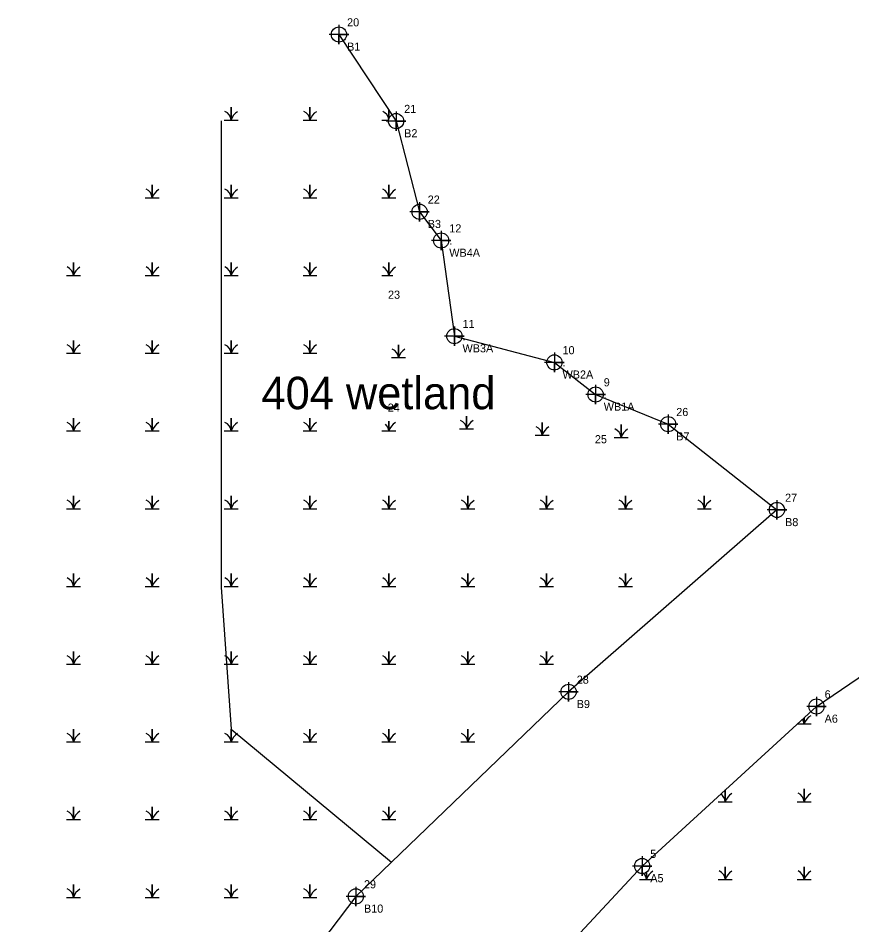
# Model space of a CAD drawing. Extents: x 2678633 to 2679425, y 623836 to 624637.
# Drawn here: x 2678971 to 2679228, y 624356.4 to 624635.8 of the extents above; entities that cross this region are included whole.
import ezdxf

# ---------------------------------------------------------------- set-up
doc = ezdxf.new("R2010")
doc.units = 0
for name, color, linetype in [('Exist Environmental Wetland Boundary', 7, 'Continuous'), ('Exist Environmental Wetland Boundary Cogo Comment', 7, 'Continuous'), ('Exist Environmental Wetland Boundary Cogo Elevation', 7, 'Continuous'), ('Exist Environmental Wetland Boundary Cogo Number', 7, 'Continuous'), ('Exist Environmental Wetland Boundary Cogo Point CELL', 7, 'Continuous'), ('Exist Environmental Wetland Boundary Text', 7, 'Continuous'), ('Exist Hydro Swamp or Marsh', 7, 'Continuous')]:
    doc.layers.add(name, color=color, linetype=linetype)

msp = doc.modelspace()

# ---------------------------------------------------------------- linework, layer by layer
at = {"layer": 'Exist Environmental Wetland Boundary'}
for points in [[(2679069.93, 624630.75), (2679087.52, 624604.07), (2679094.78, 624576.13), (2679101.43, 624567.27), (2679105.5, 624537.81), (2679136.33, 624529.73), (2679149.04, 624519.84), (2679171.39, 624510.69), (2679204.94, 624484.27), (2679140.71, 624428.23), (2679075.13, 624365.19), (2679029.64, 624305.05), (2678988.85, 624240.45), (2678945.79, 624182.95), (2678958.22, 624173.09)], [(2679033.61, 624604.18), (2679033.61, 624460.48), (2679036.68, 624416.75), (2679086.11, 624375.75)], [(2678996.94, 624177.71), (2679033.89, 624182.51), (2679071.36, 624253.6), (2679114.38, 624321.81), (2679163.39, 624374.56), (2679217.13, 624423.71), (2679286.14, 624470.62), (2679307.52, 624474.8), (2679321.51, 624489.84), (2679302.84, 624456.53), (2679292.78, 624438.21), (2679296.8, 624418.87), (2679319.66, 624396.04), (2679331.43, 624377.88), (2679317.29, 624347.71), (2679323.72, 624307.13), (2679356.11, 624275.91), (2679393.07, 624264.72), (2679417.04, 624216.21)]]:
    msp.add_lwpolyline(points, dxfattribs=at)
at = {"layer": 'Exist Environmental Wetland Boundary Cogo Point CELL'}
for points in [[(2679069.93, 624633.75), (2679069.93, 624627.75), (2679069.93, 624630.75), (2679072.93, 624630.75), (2679066.93, 624630.75)], [(2679087.52, 624607.07), (2679087.52, 624601.07), (2679087.52, 624604.07), (2679090.52, 624604.07), (2679084.52, 624604.07)], [(2679094.78, 624579.13), (2679094.78, 624573.13), (2679094.78, 624576.13), (2679097.78, 624576.13), (2679091.78, 624576.13)], [(2679101.43, 624570.27), (2679101.43, 624564.27), (2679101.43, 624567.27), (2679104.43, 624567.27), (2679098.43, 624567.27)], [(2679105.5, 624540.81), (2679105.5, 624534.81), (2679105.5, 624537.81), (2679108.5, 624537.81), (2679102.5, 624537.81)], [(2679136.33, 624532.73), (2679136.33, 624526.73), (2679136.33, 624529.73), (2679139.33, 624529.73), (2679133.33, 624529.73)], [(2679149.04, 624522.84), (2679149.04, 624516.84), (2679149.04, 624519.84), (2679152.04, 624519.84), (2679146.04, 624519.84)], [(2679171.39, 624513.69), (2679171.39, 624507.69), (2679171.39, 624510.69), (2679174.39, 624510.69), (2679168.39, 624510.69)], [(2679204.94, 624487.27), (2679204.94, 624481.27), (2679204.94, 624484.27), (2679207.94, 624484.27), (2679201.94, 624484.27)], [(2679140.71, 624431.23), (2679140.71, 624425.23), (2679140.71, 624428.23), (2679143.71, 624428.23), (2679137.71, 624428.23)], [(2679217.13, 624426.71), (2679217.13, 624420.71), (2679217.13, 624423.71), (2679220.13, 624423.71), (2679214.13, 624423.71)], [(2679163.39, 624377.56), (2679163.39, 624371.56), (2679163.39, 624374.56), (2679166.39, 624374.56), (2679160.39, 624374.56)], [(2679075.13, 624368.19), (2679075.13, 624362.19), (2679075.13, 624365.19), (2679078.13, 624365.19), (2679072.13, 624365.19)]]:
    msp.add_lwpolyline(points, dxfattribs=at)
for centre in [(2679069.93, 624630.75), (2679087.52, 624604.07), (2679094.78, 624576.13), (2679101.43, 624567.27), (2679105.5, 624537.81), (2679136.33, 624529.73), (2679149.04, 624519.84), (2679171.39, 624510.69), (2679204.94, 624484.27), (2679140.71, 624428.23), (2679217.13, 624423.71), (2679163.39, 624374.56), (2679075.13, 624365.19)]:
    msp.add_circle(centre, 2.34, dxfattribs=at)
at = {"layer": 'Exist Hydro Swamp or Marsh'}
for p, q in [((2679088.26, 624533.01), (2679088.26, 624533.01)), ((2679109.27, 624511.01), (2679109.27, 624511.01)), ((2679132.58, 624509.04), (2679132.58, 624509.04)), ((2679156.88, 624508.39), (2679156.88, 624508.39))]:
    msp.add_line(p, q, dxfattribs=at)
for points in [[(2679034.53, 624604.4), (2679036.68, 624604.4), (2679036.68, 624608.35), (2679036.68, 624604.4), (2679038.83, 624604.4)], [(2679058.84, 624604.4), (2679060.99, 624604.4), (2679060.99, 624608.35), (2679060.99, 624604.4), (2679063.14, 624604.4)], [(2679085.3, 624604.7), (2679085.3, 624607.44)], [(2679085.3, 624607.44), (2679085.3, 624604.7)], [(2679083.15, 624604.4), (2679085.25, 624604.4)], [(2679010.22, 624580.45), (2679012.37, 624580.45), (2679012.37, 624584.4), (2679012.37, 624580.45), (2679014.52, 624580.45)], [(2679034.53, 624580.45), (2679036.68, 624580.45), (2679036.68, 624584.4), (2679036.68, 624580.45), (2679038.83, 624580.45)], [(2679058.84, 624580.45), (2679060.99, 624580.45), (2679060.99, 624584.4), (2679060.99, 624580.45), (2679063.14, 624580.45)], [(2679083.15, 624580.45), (2679085.3, 624580.45), (2679085.3, 624584.4), (2679085.3, 624580.45), (2679087.45, 624580.45)], [(2678985.9, 624556.5), (2678988.05, 624556.5), (2678988.05, 624560.45), (2678988.05, 624556.5), (2678990.2, 624556.5)], [(2679010.22, 624556.5), (2679012.37, 624556.5), (2679012.37, 624560.45), (2679012.37, 624556.5), (2679014.52, 624556.5)], [(2679034.53, 624556.5), (2679036.68, 624556.5), (2679036.68, 624560.45), (2679036.68, 624556.5), (2679038.83, 624556.5)], [(2679058.84, 624556.5), (2679060.99, 624556.5), (2679060.99, 624560.45), (2679060.99, 624556.5), (2679063.14, 624556.5)], [(2679083.15, 624556.5), (2679085.3, 624556.5), (2679085.3, 624560.45), (2679085.3, 624556.5), (2679086.58, 624556.5)], [(2678985.9, 624532.55), (2678988.05, 624532.55), (2678988.05, 624536.5), (2678988.05, 624532.55), (2678990.2, 624532.55)], [(2679010.22, 624532.55), (2679012.37, 624532.55), (2679012.37, 624536.5), (2679012.37, 624532.55), (2679014.52, 624532.55)], [(2679034.53, 624532.55), (2679036.68, 624532.55), (2679036.68, 624536.5), (2679036.68, 624532.55), (2679038.83, 624532.55)], [(2679058.84, 624532.55), (2679060.99, 624532.55), (2679060.99, 624536.5), (2679060.99, 624532.55), (2679063.14, 624532.55)], [(2679086.11, 624531.23), (2679088.26, 624531.23), (2679088.26, 624535.17), (2679088.26, 624531.23), (2679090.41, 624531.23)], [(2678985.9, 624508.6), (2678988.05, 624508.6), (2678988.05, 624512.55), (2678988.05, 624508.6), (2678990.2, 624508.6)], [(2679010.22, 624508.6), (2679012.37, 624508.6), (2679012.37, 624512.55), (2679012.37, 624508.6), (2679014.52, 624508.6)], [(2679034.53, 624508.6), (2679036.68, 624508.6), (2679036.68, 624512.55), (2679036.68, 624508.6), (2679038.83, 624508.6)], [(2679058.84, 624508.6), (2679060.99, 624508.6), (2679060.99, 624512.55), (2679060.99, 624508.6), (2679063.14, 624508.6)], [(2679083.15, 624508.6), (2679085.3, 624508.6), (2679085.3, 624511.61)], [(2679085.3, 624511.61), (2679085.3, 624508.6), (2679087.45, 624508.6)], [(2679107.12, 624509.23), (2679109.27, 624509.23), (2679109.27, 624513.18), (2679109.27, 624509.23), (2679111.42, 624509.23)], [(2679130.43, 624507.26), (2679132.58, 624507.26), (2679132.58, 624511.21), (2679132.58, 624507.26), (2679134.73, 624507.26)], [(2679154.73, 624506.6), (2679156.88, 624506.6), (2679156.88, 624510.55), (2679156.88, 624506.6), (2679159.03, 624506.6)], [(2678985.9, 624484.65), (2678988.05, 624484.65), (2678988.05, 624488.6), (2678988.05, 624484.65), (2678990.2, 624484.65)], [(2679010.22, 624484.65), (2679012.37, 624484.65), (2679012.37, 624488.6), (2679012.37, 624484.65), (2679014.52, 624484.65)], [(2679034.53, 624484.65), (2679036.68, 624484.65), (2679036.68, 624488.6), (2679036.68, 624484.65), (2679038.83, 624484.65)], [(2679058.84, 624484.65), (2679060.99, 624484.65), (2679060.99, 624488.6), (2679060.99, 624484.65), (2679063.14, 624484.65)], [(2679083.15, 624484.65), (2679085.3, 624484.65), (2679085.3, 624488.6), (2679085.3, 624484.65), (2679087.45, 624484.65)], [(2679107.47, 624484.65), (2679109.62, 624484.65), (2679109.62, 624488.6), (2679109.62, 624484.65), (2679111.77, 624484.65)], [(2679131.78, 624484.65), (2679133.93, 624484.65), (2679133.93, 624488.6), (2679133.93, 624484.65), (2679136.08, 624484.65)], [(2679156.09, 624484.65), (2679158.24, 624484.65), (2679158.24, 624488.6), (2679158.24, 624484.65), (2679160.39, 624484.65)], [(2679180.4, 624484.65), (2679182.55, 624484.65), (2679182.55, 624488.6), (2679182.55, 624484.65), (2679184.7, 624484.65)], [(2678985.9, 624460.7), (2678988.05, 624460.7), (2678988.05, 624464.65), (2678988.05, 624460.7), (2678990.2, 624460.7)], [(2679010.22, 624460.7), (2679012.37, 624460.7), (2679012.37, 624464.65), (2679012.37, 624460.7), (2679014.52, 624460.7)], [(2679034.53, 624460.7), (2679036.68, 624460.7), (2679036.68, 624464.65), (2679036.68, 624460.7), (2679038.83, 624460.7)], [(2679058.84, 624460.7), (2679060.99, 624460.7), (2679060.99, 624464.65), (2679060.99, 624460.7), (2679063.14, 624460.7)], [(2679083.15, 624460.7), (2679085.3, 624460.7), (2679085.3, 624464.65), (2679085.3, 624460.7), (2679087.45, 624460.7)], [(2679107.47, 624460.7), (2679109.62, 624460.7), (2679109.62, 624464.65), (2679109.62, 624460.7), (2679111.77, 624460.7)], [(2679131.78, 624460.7), (2679133.93, 624460.7), (2679133.93, 624464.65), (2679133.93, 624460.7), (2679136.08, 624460.7)], [(2679156.09, 624460.7), (2679158.24, 624460.7), (2679158.24, 624464.65), (2679158.24, 624460.7), (2679160.39, 624460.7)], [(2678985.9, 624436.75), (2678988.05, 624436.75), (2678988.05, 624440.7), (2678988.05, 624436.75), (2678990.2, 624436.75)], [(2679010.22, 624436.75), (2679012.37, 624436.75), (2679012.37, 624440.7), (2679012.37, 624436.75), (2679014.52, 624436.75)], [(2679034.53, 624436.75), (2679036.68, 624436.75), (2679036.68, 624440.7), (2679036.68, 624436.75), (2679038.83, 624436.75)], [(2679058.84, 624436.75), (2679060.99, 624436.75), (2679060.99, 624440.7), (2679060.99, 624436.75), (2679063.14, 624436.75)], [(2679083.15, 624436.75), (2679085.3, 624436.75), (2679085.3, 624440.7), (2679085.3, 624436.75), (2679087.45, 624436.75)], [(2679107.47, 624436.75), (2679109.62, 624436.75), (2679109.62, 624440.7), (2679109.62, 624436.75), (2679111.77, 624436.75)], [(2679131.78, 624436.75), (2679133.93, 624436.75), (2679133.93, 624440.7), (2679133.93, 624436.75), (2679136.08, 624436.75)], [(2679211.23, 624418.32), (2679213.33, 624418.32), (2679213.33, 624420.24)], [(2679213.33, 624420.24), (2679213.33, 624418.32), (2679215.48, 624418.32)], [(2678985.9, 624412.8), (2678988.05, 624412.8), (2678988.05, 624416.75), (2678988.05, 624412.8), (2678990.2, 624412.8)], [(2679010.22, 624412.8), (2679012.37, 624412.8), (2679012.37, 624416.75), (2679012.37, 624412.8), (2679014.52, 624412.8)], [(2679034.53, 624412.8), (2679036.68, 624412.8), (2679036.68, 624416.75), (2679036.68, 624412.8), (2679038.83, 624412.8)], [(2679058.84, 624412.8), (2679060.99, 624412.8), (2679060.99, 624416.75), (2679060.99, 624412.8), (2679063.14, 624412.8)], [(2679083.15, 624412.8), (2679085.3, 624412.8), (2679085.3, 624416.75), (2679085.3, 624412.8), (2679087.45, 624412.8)], [(2679107.47, 624412.8), (2679109.62, 624412.8), (2679109.62, 624416.75), (2679109.62, 624412.8), (2679111.77, 624412.8)], [(2679186.86, 624394.37), (2679189.01, 624394.37), (2679189.01, 624398)], [(2679189.01, 624398), (2679189.01, 624394.37), (2679191.17, 624394.37)], [(2679211.18, 624394.37), (2679213.33, 624394.37), (2679213.33, 624398.31), (2679213.33, 624394.37), (2679215.48, 624394.37)], [(2678985.9, 624388.85), (2678988.05, 624388.85), (2678988.05, 624392.8), (2678988.05, 624388.85), (2678990.2, 624388.85)], [(2679010.22, 624388.85), (2679012.37, 624388.85), (2679012.37, 624392.8), (2679012.37, 624388.85), (2679014.52, 624388.85)], [(2679034.53, 624388.85), (2679036.68, 624388.85), (2679036.68, 624392.8), (2679036.68, 624388.85), (2679038.83, 624388.85)], [(2679058.84, 624388.85), (2679060.99, 624388.85), (2679060.99, 624392.8), (2679060.99, 624388.85), (2679063.14, 624388.85)], [(2679083.15, 624388.85), (2679085.3, 624388.85), (2679085.3, 624392.8), (2679085.3, 624388.85), (2679087.45, 624388.85)], [(2679186.86, 624370.42), (2679189.01, 624370.42), (2679189.01, 624374.36), (2679189.01, 624370.42), (2679191.17, 624370.42)], [(2679211.18, 624370.42), (2679213.33, 624370.42), (2679213.33, 624374.36), (2679213.33, 624370.42), (2679215.48, 624370.42)], [(2679162.55, 624370.42), (2679164.7, 624370.42), (2679164.7, 624372.67)], [(2679164.7, 624372.67), (2679164.7, 624370.42), (2679166.85, 624370.42)], [(2678985.9, 624364.9), (2678988.05, 624364.9), (2678988.05, 624368.85), (2678988.05, 624364.9), (2678990.2, 624364.9)], [(2679010.22, 624364.9), (2679012.37, 624364.9), (2679012.37, 624368.85), (2679012.37, 624364.9), (2679014.52, 624364.9)], [(2679034.53, 624364.9), (2679036.68, 624364.9), (2679036.68, 624368.85), (2679036.68, 624364.9), (2679038.83, 624364.9)], [(2679058.84, 624364.9), (2679060.99, 624364.9), (2679060.99, 624368.85), (2679060.99, 624364.9), (2679063.14, 624364.9)]]:
    msp.add_lwpolyline(points, dxfattribs=at)
for centre, radius, start, end in [((2679033.61, 624604.18), 3.07, 4.1403, 67.535), ((2679041.24, 624602.89), 4.81, 122.1274, 161.6222), ((2679057.92, 624604.18), 3.07, 4.1403, 67.535), ((2679065.55, 624602.89), 4.81, 122.1274, 161.6222), ((2679082.24, 624604.18), 3.07, 7.7072, 67.535), ((2679089.86, 624602.89), 4.81, 139.1466, 139.8748), ((2679009.3, 624580.23), 3.07, 4.1403, 67.535), ((2679033.61, 624580.23), 3.07, 4.1403, 67.535), ((2679057.92, 624580.23), 3.07, 4.1403, 67.535), ((2679082.24, 624580.23), 3.07, 4.1403, 67.535), ((2679016.93, 624578.94), 4.81, 122.1274, 161.6222), ((2679041.24, 624578.94), 4.81, 122.1274, 161.6222), ((2679065.55, 624578.94), 4.81, 122.1274, 161.6222), ((2679089.86, 624578.94), 4.81, 122.1274, 161.6222), ((2678984.99, 624556.28), 3.07, 4.1403, 67.535), ((2678992.61, 624554.99), 4.81, 122.1274, 161.6222), ((2679009.3, 624556.28), 3.07, 4.1403, 67.535), ((2679016.93, 624554.99), 4.81, 122.1274, 161.6222), ((2679033.61, 624556.28), 3.07, 4.1403, 67.535), ((2679041.24, 624554.99), 4.81, 122.1274, 161.6222), ((2679057.92, 624556.28), 3.07, 4.1403, 67.535), ((2679065.55, 624554.99), 4.81, 122.1274, 161.6222), ((2679082.24, 624556.28), 3.07, 4.1403, 67.535), ((2679089.86, 624554.99), 4.81, 122.1274, 161.6222), ((2678984.99, 624532.33), 3.07, 4.1403, 67.535), ((2678992.61, 624531.04), 4.81, 122.1274, 161.6222), ((2679009.3, 624532.33), 3.07, 4.1403, 67.535), ((2679016.93, 624531.04), 4.81, 122.1274, 161.6222), ((2679033.61, 624532.33), 3.07, 4.1403, 67.535), ((2679041.24, 624531.04), 4.81, 122.1274, 161.6222), ((2679057.92, 624532.33), 3.07, 4.1403, 67.535), ((2679065.55, 624531.04), 4.81, 122.1274, 161.6222), ((2679085.19, 624531.01), 3.07, 4.1403, 67.535), ((2679092.82, 624529.71), 4.81, 122.1274, 161.6222), ((2678984.99, 624508.38), 3.07, 4.1403, 67.535), ((2678992.61, 624507.09), 4.81, 122.1274, 161.6222), ((2679009.3, 624508.38), 3.07, 4.1403, 67.535), ((2679016.93, 624507.09), 4.81, 122.1274, 161.6222), ((2679033.61, 624508.38), 3.07, 4.1403, 67.535), ((2679041.24, 624507.09), 4.81, 122.1274, 161.6222), ((2679057.92, 624508.38), 3.07, 4.1403, 67.535), ((2679065.55, 624507.09), 4.81, 122.1274, 161.6222), ((2679082.24, 624508.38), 3.07, 4.1403, 47.7553), ((2679089.86, 624507.09), 4.81, 122.1274, 161.6222), ((2679106.21, 624509.01), 3.07, 4.1403, 67.535), ((2679113.83, 624507.72), 4.81, 122.1274, 161.6222), ((2679129.52, 624507.04), 3.07, 4.1403, 67.535), ((2679137.14, 624505.75), 4.81, 122.1274, 161.6222), ((2679153.81, 624506.38), 3.07, 4.1403, 67.535), ((2679161.44, 624505.09), 4.81, 122.1274, 161.6222), ((2678984.99, 624484.43), 3.07, 4.1403, 67.535), ((2678992.61, 624483.14), 4.81, 122.1274, 161.6222), ((2679009.3, 624484.43), 3.07, 4.1403, 67.535), ((2679016.93, 624483.14), 4.81, 122.1274, 161.6222), ((2679033.61, 624484.43), 3.07, 4.1403, 67.535), ((2679041.24, 624483.14), 4.81, 122.1274, 161.6222), ((2679057.92, 624484.43), 3.07, 4.1403, 67.535), ((2679065.55, 624483.14), 4.81, 122.1274, 161.6222), ((2679082.24, 624484.43), 3.07, 4.1403, 67.535), ((2679089.86, 624483.14), 4.81, 122.1274, 161.6222), ((2679106.55, 624484.43), 3.07, 4.1403, 67.535), ((2679114.18, 624483.14), 4.81, 122.1274, 161.6222), ((2679130.86, 624484.43), 3.07, 4.1403, 67.535), ((2679138.49, 624483.14), 4.81, 122.1274, 161.6222), ((2679155.17, 624484.43), 3.07, 4.1403, 67.535), ((2679162.8, 624483.14), 4.81, 122.1274, 161.6222), ((2679179.49, 624484.43), 3.07, 4.1403, 67.535), ((2679187.11, 624483.14), 4.81, 122.1274, 161.6222), ((2678984.99, 624460.48), 3.07, 4.1403, 67.535), ((2678992.61, 624459.19), 4.81, 122.1274, 161.6222), ((2679009.3, 624460.48), 3.07, 4.1403, 67.535), ((2679016.93, 624459.19), 4.81, 122.1274, 161.6222), ((2679033.61, 624460.48), 3.07, 4.1403, 67.535), ((2679041.24, 624459.19), 4.81, 122.1274, 161.6222), ((2679057.92, 624460.48), 3.07, 4.1403, 67.535), ((2679065.55, 624459.19), 4.81, 122.1274, 161.6222), ((2679082.24, 624460.48), 3.07, 4.1403, 67.535), ((2679089.86, 624459.19), 4.81, 122.1274, 161.6222), ((2679106.55, 624460.48), 3.07, 4.1403, 67.535), ((2679114.18, 624459.19), 4.81, 122.1274, 161.6222), ((2679130.86, 624460.48), 3.07, 4.1403, 67.535), ((2679138.49, 624459.19), 4.81, 122.1274, 161.6222), ((2679155.17, 624460.48), 3.07, 4.1403, 67.535), ((2679162.8, 624459.19), 4.81, 122.1274, 161.6222), ((2679179.49, 624460.48), 3.07, 63.9969, 67.535), ((2678984.99, 624436.53), 3.07, 4.1403, 67.535), ((2678992.61, 624435.24), 4.81, 122.1274, 161.6222), ((2679009.3, 624436.53), 3.07, 4.1403, 67.535), ((2679016.93, 624435.24), 4.81, 122.1274, 161.6222), ((2679033.61, 624436.53), 3.07, 4.1403, 67.535), ((2679041.24, 624435.24), 4.81, 122.1274, 161.6222), ((2679057.92, 624436.53), 3.07, 4.1403, 67.535), ((2679065.55, 624435.24), 4.81, 122.1274, 161.6222), ((2679082.24, 624436.53), 3.07, 4.1403, 67.535), ((2679089.86, 624435.24), 4.81, 122.1274, 161.6222), ((2679106.55, 624436.53), 3.07, 4.1403, 67.535), ((2679114.18, 624435.24), 4.81, 122.1274, 161.6222), ((2679130.86, 624436.53), 3.07, 4.1403, 67.535), ((2679138.49, 624435.24), 4.81, 122.1274, 161.6222), ((2679210.26, 624418.1), 3.07, 4.1403, 33.2476), ((2679217.89, 624416.8), 4.81, 122.1274, 161.6222), ((2678984.99, 624412.58), 3.07, 4.1403, 67.535), ((2679009.3, 624412.58), 3.07, 4.1403, 67.535), ((2679033.61, 624412.58), 3.07, 4.1403, 67.535), ((2679057.92, 624412.58), 3.07, 4.1403, 67.535), ((2679082.24, 624412.58), 3.07, 4.1403, 67.535), ((2679106.55, 624412.58), 3.07, 4.1403, 67.535), ((2678992.61, 624411.29), 4.81, 122.1274, 161.6222), ((2679016.93, 624411.29), 4.81, 122.1274, 161.6222), ((2679041.24, 624411.29), 4.81, 122.1274, 161.6222), ((2679065.55, 624411.29), 4.81, 122.1274, 161.6222), ((2679089.86, 624411.29), 4.81, 122.1274, 161.6222), ((2679114.18, 624411.29), 4.81, 122.1274, 161.6222), ((2679185.95, 624394.15), 3.07, 4.1403, 56.9801), ((2679193.58, 624392.85), 4.81, 122.1274, 161.6222), ((2679210.26, 624394.15), 3.07, 4.1403, 67.535), ((2679217.89, 624392.85), 4.81, 122.1274, 161.6222), ((2678984.99, 624388.63), 3.07, 4.1403, 67.535), ((2678992.61, 624387.34), 4.81, 122.1274, 161.6222), ((2679009.3, 624388.63), 3.07, 4.1403, 67.535), ((2679016.93, 624387.34), 4.81, 122.1274, 161.6222), ((2679033.61, 624388.63), 3.07, 4.1403, 67.535), ((2679041.24, 624387.34), 4.81, 122.1274, 161.6222), ((2679057.92, 624388.63), 3.07, 4.1403, 67.535), ((2679065.55, 624387.34), 4.81, 122.1274, 161.6222), ((2679082.24, 624388.63), 3.07, 4.1403, 67.535), ((2679089.86, 624387.34), 4.81, 122.1274, 161.6222), ((2679161.64, 624370.2), 3.07, 4.1403, 43.3721), ((2679169.26, 624368.9), 4.81, 122.1274, 161.6222), ((2679185.95, 624370.2), 3.07, 4.1403, 67.535), ((2679193.58, 624368.9), 4.81, 122.1274, 161.6222), ((2679210.26, 624370.2), 3.07, 4.1403, 67.535), ((2679217.89, 624368.9), 4.81, 122.1274, 161.6222), ((2678984.99, 624364.68), 3.07, 4.1403, 67.535), ((2678992.61, 624363.39), 4.81, 122.1274, 161.6222), ((2679009.3, 624364.68), 3.07, 4.1403, 67.535), ((2679016.93, 624363.39), 4.81, 122.1274, 161.6222), ((2679033.61, 624364.68), 3.07, 4.1403, 67.535), ((2679041.24, 624363.39), 4.81, 122.1274, 161.6222), ((2679057.92, 624364.68), 3.07, 4.1403, 67.535), ((2679065.55, 624363.39), 4.81, 122.1274, 161.6222)]:
    msp.add_arc(centre, radius, start, end, dxfattribs=at)

# ---------------------------------------------------------------- texts
at = {"layer": 'Exist Environmental Wetland Boundary Cogo Comment'}
for s, p in [('B1', (2679072.43, 624625.75)), ('B2', (2679090.02, 624599.07)), ('B3', (2679097.28, 624571.13)), ('WB4A', (2679103.93, 624562.27)), ('WB3A', (2679108, 624532.81)), ('WB2A', (2679138.83, 624524.73)), ('WB1A', (2679151.54, 624514.84)), ('B7', (2679173.89, 624505.69)), ('B8', (2679207.44, 624479.27)), ('B9', (2679143.21, 624423.23)), ('A6', (2679219.63, 624418.71)), ('A5', (2679165.89, 624369.56)), ('B10', (2679077.63, 624360.19))]:
    msp.add_text(s, height=2.5, dxfattribs=at).set_placement(p)
at = {"layer": 'Exist Environmental Wetland Boundary Cogo Elevation'}
for p in [(2679103.93, 624566.02), (2679108, 624536.56), (2679138.83, 624528.48), (2679151.54, 624518.59)]:
    msp.add_text('.', height=2.5, dxfattribs=at).set_placement(p)
at = {"layer": 'Exist Environmental Wetland Boundary Cogo Number'}
for s, p in [('20', (2679072.43, 624633.25)), ('21', (2679090.02, 624606.57)), ('22', (2679097.28, 624578.63)), ('12', (2679103.93, 624569.77)), ('23', (2679085.04, 624549.33)), ('11', (2679108, 624540.31)), ('10', (2679138.83, 624532.23)), ('9', (2679151.54, 624522.34)), ('24', (2679084.95, 624514.54)), ('26', (2679173.89, 624513.19)), ('25', (2679148.82, 624504.81)), ('27', (2679207.44, 624486.77)), ('28', (2679143.21, 624430.73)), ('6', (2679219.63, 624426.21)), ('5', (2679165.89, 624377.06)), ('29', (2679077.63, 624367.69))]:
    msp.add_text(s, height=2.5, dxfattribs=at).set_placement(p)
at = {"layer": 'Exist Environmental Wetland Boundary Text'}
msp.add_text('404 wetland', height=10, dxfattribs=at).set_placement((2679046.04, 624515.29))

doc.saveas('drawing.dxf')
